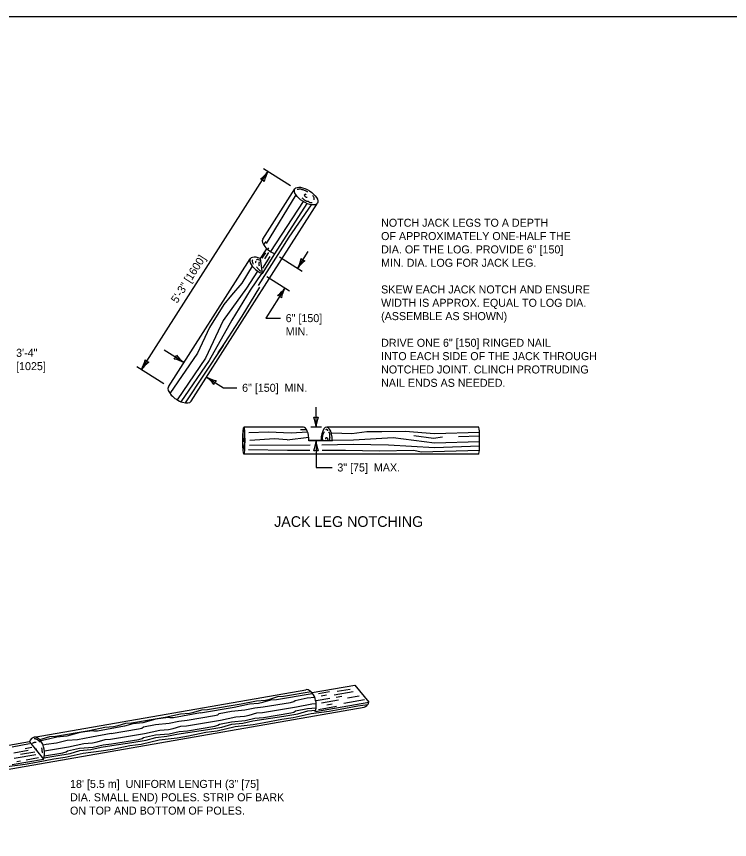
# Model space of a CAD drawing. Extents: x 49991.4 to 50021, y 49987.6 to 50011.4.
# Drawn here: x 50003.34 to 50008.69, y 49992.83 to 49999 of the extents above; entities that cross this region are included whole.
import ezdxf

# ---------------------------------------------------------------- set-up
doc = ezdxf.new("R2010")
doc.units = 0
for name, color, linetype in [('Level 1', 7, 'Continuous'), ('Level 2', 7, 'Continuous'), ('Level 3', 7, 'Continuous')]:
    doc.layers.add(name, color=color, linetype=linetype)

msp = doc.modelspace()

# ---------------------------------------------------------------- linework, layer by layer
at = {"layer": 'Level 1'}
for p, q in [((50005.1905, 49997.3295), (50005.4315, 49997.707)), ((50005.3496, 49997.2048), (50005.6009, 49997.5986)), ((50005.2014, 49997.2915), (50005.2152, 49997.313)), ((50005.1738, 49997.1841), (50005.2212, 49997.2583)), ((50005.1867, 49997.1869), (50005.2128, 49997.2278)), ((50005.2072, 49997.1826), (50005.237, 49997.2293)), ((50005.2283, 49997.2521), (50005.2365, 49997.265)), ((50004.4838, 49996.2226), (50005.097, 49997.183)), ((50004.6533, 49996.1142), (50005.3496, 49997.2048)), ((50005.141, 49997.1638), (50005.1418, 49997.164)), ((50005.1439, 49997.1757), (50005.1499, 49997.1769)), ((50005.1615, 49997.1757), (50005.1672, 49997.1734)), ((50005.1879, 49997.0719), (50005.1738, 49997.1841)), ((50005.1879, 49997.0719), (50005.282, 49997.2193)), ((50005.1907, 49997.1129), (50005.2462, 49997.1998)), ((50005.1373, 49997.1603), (50005.1374, 49997.1605)), ((50005.1375, 49997.1607), (50005.1378, 49997.1613)), ((50005.1394, 49997.1522), (50005.1375, 49997.1548)), ((50005.161, 49997.1447), (50005.161, 49997.1451)), ((50005.1676, 49997.1285), (50005.1647, 49997.1326)), ((50005.1653, 49997.157), (50005.1669, 49997.159)), ((50005.495, 49995.9203), (50005.0483, 49995.9203)), ((50005.5194, 49995.9016), (50005.4736, 49995.9016)), ((50006.8094, 49995.9203), (50005.6699, 49995.9203)), ((50005.6281, 49995.8211), (50005.537, 49995.8211)), ((50005.7119, 49995.8183), (50005.537, 49995.8183)), ((50005.6281, 49995.8211), (50005.7119, 49995.8183)), ((50006.816, 49995.8525), (50006.6578, 49995.8478)), ((50006.8094, 49995.7191), (50005.0483, 49995.7191)), ((50005.5599, 49993.9305), (50005.8806, 49993.9866)), ((50005.7483, 49993.9404), (50005.8449, 49993.9573)), ((50005.8806, 49993.9866), (50005.9865, 49993.8591)), ((50003.4771, 49993.5964), (50005.5129, 49993.9521)), ((50005.6077, 49993.9234), (50005.6902, 49993.9378)), ((50005.6283, 49993.9063), (50005.6688, 49993.9134)), ((50005.7266, 49993.9138), (50005.8681, 49993.9384)), ((50005.7419, 49993.8961), (50005.7824, 49993.9031)), ((50005.8257, 49993.891), (50005.9125, 49993.9062)), ((50005.5849, 49993.7889), (50005.9865, 49993.8591)), ((50005.5908, 49993.8718), (50005.6925, 49993.8896)), ((50005.6318, 49993.8547), (50005.7592, 49993.877)), ((50005.6714, 49993.8397), (50005.7118, 49993.8468)), ((50005.7988, 49993.8522), (50005.9524, 49993.879)), ((50000.9144, 49992.9433), (50005.951, 49993.8227)), ((50005.6076, 49993.8043), (50005.7433, 49993.8279)), ((50003.4416, 49993.5605), (50003.2869, 49993.5335)), ((50003.4436, 49993.5457), (50003.3119, 49993.5226)), ((50003.4416, 49993.5605), (50003.5478, 49993.433)), ((50003.4314, 49993.4959), (50003.3243, 49993.4772)), ((50003.4907, 49993.465), (50003.3277, 49993.4365)), ((50003.4812, 49993.4855), (50003.3745, 49993.4668)), ((50003.46, 49993.5189), (50003.411, 49993.5104)), ((50003.3119, 49993.3918), (50003.5478, 49993.433)), ((50003.3757, 49993.4167), (50003.3464, 49993.4116)), ((50003.5108, 49993.4407), (50003.4181, 49993.4244))]:
    msp.add_line(p, q, dxfattribs=at)
msp.add_lwpolyline([(49999.3835, 49998.9992), (50016.7501, 49998.9992), (50016.7501, 49987.7988), (49999.3835, 49987.7988)], close=True, dxfattribs=at)
for points in [[(50005.4393, 49997.6622), (50005.2168, 49997.2978)], [(50005.4925, 49997.6126), (50005.2499, 49997.2362)], [(50005.5219, 49997.5972), (50005.2792, 49997.2205)], [(50005.5546, 49997.5873), (50005.3858, 49997.346), (50005.1567, 49996.9819)], [(50005.1123, 49997.1264), (50005.0346, 49996.9991), (50004.9559, 49996.9091), (50004.8996, 49996.8396), (50004.7922, 49996.6675), (50004.7028, 49996.4757), (50004.4955, 49996.1723)], [(50005.1526, 49997.0894), (50005.069, 49996.9637), (50004.8934, 49996.7212), (50004.762, 49996.4385), (50004.5485, 49996.126)], [(50005.1815, 49997.0734), (50005.097, 49996.9463), (50004.9592, 49996.7218), (50004.7896, 49996.4207), (50004.5779, 49996.1114)], [(50005.167, 49996.9711), (50005.0336, 49996.7532), (50004.8554, 49996.4766), (50004.8933, 49996.5334), (50004.6098, 49996.1025)], [(50005.5272, 49995.8842), (50005.4029, 49995.8764), (50005.2327, 49995.8841), (50005.0861, 49995.8786)], [(50005.7082, 49995.877), (50005.8585, 49995.8739), (50005.97, 49995.8869), (50006.0835, 49995.8888), (50006.259, 49995.8902), (50006.4782, 49995.8719), (50006.8149, 49995.8824)], [(50005.3725, 49995.8266), (50005.2783, 49995.8322), (50005.0949, 49995.8198)], [(50005.3725, 49995.8266), (50005.5355, 49995.8461)], [(50005.7165, 49995.8231), (50005.8698, 49995.8259), (50006.1687, 49995.8434), (50006.4777, 49995.802), (50006.8164, 49995.8126)], [(50006.5385, 49995.8455), (50006.471, 49995.8346), (50006.3225, 49995.8558)], [(50005.0829, 49995.7521), (50005.3766, 49995.7493), (50005.5445, 49995.7486)], [(50005.0921, 49995.7851), (50005.5455, 49995.7869)], [(50005.6341, 49995.7886), (50005.8694, 49995.793), (50006.1328, 49995.7882), (50006.4779, 49995.7692), (50006.8159, 49995.78)], [(50005.6353, 49995.7481), (50005.8108, 49995.7473)], [(50005.8108, 49995.7473), (50006.0663, 49995.7424), (50006.3231, 49995.7472), (50006.3792, 49995.7355), (50006.8144, 49995.7486)], [(50004.7765, 49993.8042), (50005.0296, 49993.8461), (50005.1448, 49993.8701), (50005.2101, 49993.8751), (50005.2448, 49993.8824), (50005.3034, 49993.9005), (50005.346, 49993.9038)], [(50005.1942, 49993.8236), (50005.3984, 49993.8573), (50005.4231, 49993.8641), (50005.4345, 49993.8727), (50005.5246, 49993.8911), (50005.5801, 49993.8958)], [(50005.2935, 49993.8795), (50005.5467, 49993.9213), (50005.5643, 49993.925)], [(50005.346, 49993.9038), (50005.5529, 49993.938)], [(50004.724, 49993.78), (50004.9771, 49993.8219), (50005.0923, 49993.8458), (50005.1577, 49993.8507), (50005.1923, 49993.858), (50005.2511, 49993.8762), (50005.2935, 49993.8795)], [(50005.1895, 49993.7818), (50005.4425, 49993.8235), (50005.5577, 49993.8475), (50005.5912, 49993.8501)], [(50005.7717, 49993.8061), (50005.9026, 49993.8323), (50005.9783, 49993.8425)], [(50004.724, 49993.78), (50004.5206, 49993.7425), (50004.4949, 49993.7405), (50004.4814, 49993.7446), (50004.3903, 49993.7314), (50004.2911, 49993.7049), (50004.2165, 49993.6958), (50004.1547, 49993.6804)], [(50004.207, 49993.7049), (50004.4602, 49993.7467), (50004.5753, 49993.7707), (50004.6407, 49993.7756), (50004.6753, 49993.7829), (50004.7341, 49993.801), (50004.7765, 49993.8042)], [(50004.6201, 49993.6823), (50004.8732, 49993.7239), (50004.9883, 49993.748), (50005.0537, 49993.7529), (50005.0883, 49993.7604), (50005.1472, 49993.7784), (50005.1895, 49993.7818)], [(50004.6249, 49993.7242), (50004.8291, 49993.7579), (50004.8536, 49993.7647), (50004.8652, 49993.7733), (50004.9553, 49993.7918), (50005.0576, 49993.8004), (50005.1309, 49993.8171), (50005.1942, 49993.8236)], [(50005.1959, 49993.7447), (50005.4, 49993.7783), (50005.4248, 49993.7851), (50005.4362, 49993.7938), (50005.5264, 49993.8122), (50005.5913, 49993.8177)], [(50005.1981, 49993.732), (50005.3481, 49993.7549), (50005.4544, 49993.772), (50005.5281, 49993.7943), (50005.5882, 49993.7999)], [(50005.2024, 49993.7066), (50005.3332, 49993.7327), (50005.4188, 49993.7446), (50005.5531, 49993.775), (50005.6884, 49993.7916), (50005.7717, 49993.8061)], [(50004.0556, 49993.6249), (50004.2597, 49993.6584), (50004.2844, 49993.6654), (50004.2958, 49993.6739), (50004.386, 49993.6924), (50004.4882, 49993.701), (50004.5615, 49993.7177), (50004.6249, 49993.7242)], [(50004.6265, 49993.6451), (50004.8306, 49993.6787), (50004.8553, 49993.6856), (50004.8669, 49993.6942), (50004.957, 49993.7127), (50005.0592, 49993.7213), (50005.1324, 49993.7381), (50005.1959, 49993.7447)], [(50004.6287, 49993.6325), (50004.7786, 49993.6554), (50004.885, 49993.6726), (50004.9588, 49993.6949), (50005.0409, 49993.7024), (50005.117, 49993.7197), (50005.1981, 49993.732)], [(50004.1547, 49993.6804), (50003.9512, 49993.6429), (50003.9256, 49993.641), (50003.9121, 49993.645), (50003.821, 49993.6318), (50003.7218, 49993.6054), (50003.6473, 49993.5962), (50003.5855, 49993.5809)], [(50003.6376, 49993.6054), (50003.8907, 49993.6471), (50004.0059, 49993.6712), (50004.0712, 49993.6761), (50004.1059, 49993.6835), (50004.1646, 49993.7016), (50004.207, 49993.7049)], [(50004.0506, 49993.5827), (50004.3037, 49993.6246), (50004.4189, 49993.6485), (50004.4843, 49993.6535), (50004.519, 49993.6609), (50004.5777, 49993.679), (50004.6201, 49993.6823)], [(50004.6331, 49993.6072), (50004.7639, 49993.6333), (50004.8495, 49993.6451), (50004.9838, 49993.6756), (50005.1189, 49993.6921), (50005.2024, 49993.7066)], [(50003.5179, 49993.58), (50003.5365, 49993.584), (50003.5952, 49993.6021), (50003.6376, 49993.6054)], [(50004.0556, 49993.6249), (50003.9068, 49993.5955), (50003.801, 49993.5758), (50003.7241, 49993.5716), (50003.6442, 49993.5509), (50003.5667, 49993.5413), (50003.5442, 49993.5369)], [(50004.0572, 49993.5457), (50004.2612, 49993.5793), (50004.286, 49993.5863), (50004.2975, 49993.5948), (50004.3876, 49993.6132), (50004.4898, 49993.6219), (50004.5631, 49993.6386), (50004.6265, 49993.6451)], [(50004.0594, 49993.5331), (50004.2093, 49993.5559), (50004.3157, 49993.5731), (50004.3894, 49993.5954), (50004.4715, 49993.6031), (50004.5476, 49993.6203), (50004.6287, 49993.6325)], [(50004.0638, 49993.5077), (50004.1945, 49993.5338), (50004.2801, 49993.5454), (50004.4144, 49993.5762), (50004.5496, 49993.5927), (50004.6331, 49993.6072)], [(50003.5855, 49993.5809), (50003.5265, 49993.57)], [(50003.5508, 49993.4429), (50003.6399, 49993.4564), (50003.7463, 49993.4738), (50003.8199, 49993.4958), (50003.9022, 49993.5037), (50003.9784, 49993.5208), (50004.0594, 49993.5331)], [(50003.5536, 49993.457), (50003.692, 49993.4799), (50003.7167, 49993.4868), (50003.7281, 49993.4952), (50003.8183, 49993.5138), (50003.9205, 49993.5224), (50003.9938, 49993.5391), (50004.0572, 49993.5457)], [(50003.554, 49993.4953), (50003.7345, 49993.5251), (50003.8497, 49993.5491), (50003.915, 49993.554), (50003.9496, 49993.5615), (50004.0083, 49993.5795), (50004.0506, 49993.5827)], [(50003.4943, 49993.4082), (50003.6251, 49993.4343), (50003.7108, 49993.446), (50003.8452, 49993.4766), (50003.9803, 49993.4932), (50004.0638, 49993.5077)], [(50002.925, 49993.3087), (50003.0558, 49993.3348), (50003.1413, 49993.3467), (50003.2756, 49993.3771), (50003.4108, 49993.3937), (50003.4943, 49993.4082)]]:
    msp.add_lwpolyline(points, dxfattribs=at)
for centre, radius, start, end in [((50005.1422, 49997.1589), 0.005, 103.51797, 151.39124), ((50005.1538, 49997.1573), 0.02, 67.59208, 101.26791), ((50005.1415, 49997.1578), 0.005, 149.082, 215.75362), ((50005.1331, 49997.1631), 0.005, 329.082, 331.39124), ((50005.181, 49997.1446), 0.02, 141.84409, 178.59483), ((50005.181, 49997.1442), 0.02, 178.59483, 215.47596)]:
    msp.add_arc(centre, radius, start, end, dxfattribs=at)
for centre, major_axis, ratio in [((50005.5162, 49997.6528), (-0.0847, 0.0542), 0.462929), ((50005.0483, 49995.8197), (0, 0.1006), 0.069439)]:
    msp.add_ellipse(centre, major_axis=major_axis, ratio=ratio, dxfattribs=at)
for centre, major_axis, ratio, start_param, end_param in [((50005.2752, 49997.2753), (-0.0847, 0.0542), 0.462929, 0, 1.935586), ((50005.1811, 49997.1279), (-0.0847, 0.0542), 0.462929, 5.082678, 8.21875), ((50004.5685, 49996.1684), (-0.0847, 0.0542), 0.462929, 6.283184, 9.425644), ((50005.4951, 49995.8197), (-0.0001, 0.1006), 0.416637, 4.698139, 6.283283), ((50005.67, 49995.8197), (-0.0001, 0.1006), 0.416637, 4.698139, 7.839732), ((50006.8094, 49995.8197), (0, 0.1006), 0.069439, 3.141147, 6.283606), ((50005.5317, 49993.8525), (-0.0175, 0.0999), 0.577493, 3.925489, 6.306126), ((50005.9334, 49993.9226), (-0.0175, 0.0999), 0.577493, 3.141466, 3.926391), ((50003.4946, 49993.4966), (-0.0175, 0.0999), 0.577493, 3.925612, 7.06337)]:
    msp.add_ellipse(centre, major_axis=major_axis, ratio=ratio, start_param=start_param, end_param=end_param, dxfattribs=at)
for points in [[(50005.5291, 49997.6809), (50005.5037, 49997.6954), (50005.4815, 49997.7024), (50005.4722, 49997.7049), (50005.4493, 49997.7012)], [(50005.5163, 49997.662), (50005.509, 49997.6662), (50005.5032, 49997.663), (50005.5026, 49997.6559), (50005.5061, 49997.652), (50005.515, 49997.6442), (50005.5225, 49997.6436)], [(50005.5633, 49997.6585), (50005.5684, 49997.6509), (50005.5734, 49997.6416), (50005.5745, 49997.6307), (50005.5741, 49997.6253)], [(50005.4825, 49997.6394), (50005.4933, 49997.6332), (50005.5039, 49997.6234), (50005.5167, 49997.6171), (50005.5185, 49997.6151), (50005.5241, 49997.6147), (50005.537, 49997.6101), (50005.5424, 49997.6061), (50005.5517, 49997.6037), (50005.5612, 49997.6047)], [(50005.1214, 49997.1414), (50005.1175, 49997.1496), (50005.1139, 49997.1596), (50005.1145, 49997.1705), (50005.1157, 49997.1758)], [(50005.1445, 49997.1218), (50005.1523, 49997.1123), (50005.1616, 49997.1018), (50005.1737, 49997.093), (50005.1773, 49997.091)], [(50005.0437, 49995.824), (50005.0439, 49995.8532), (50005.0448, 49995.8757), (50005.0453, 49995.8848), (50005.0476, 49995.9022)], [(50005.6399, 49995.826), (50005.6393, 49995.8487), (50005.6457, 49995.874), (50005.6527, 49995.8863)], [(50005.6637, 49995.9029), (50005.6639, 49995.9032), (50005.6645, 49995.9037), (50005.6653, 49995.9042), (50005.6657, 49995.9045), (50005.6661, 49995.9047), (50005.667, 49995.9051), (50005.6678, 49995.9054), (50005.6682, 49995.9054), (50005.6684, 49995.9055), (50005.6685, 49995.9055), (50005.6686, 49995.9055), (50005.6689, 49995.9054), (50005.6693, 49995.9054), (50005.67, 49995.9051), (50005.6705, 49995.9049), (50005.6709, 49995.9047), (50005.6713, 49995.9044), (50005.6716, 49995.9042), (50005.6731, 49995.9031), (50005.6737, 49995.9026), (50005.674, 49995.9023), (50005.6742, 49995.9021), (50005.6748, 49995.9014), (50005.675, 49995.9011), (50005.6752, 49995.9008), (50005.6754, 49995.9002), (50005.6755, 49995.8996), (50005.6755, 49995.8989), (50005.6754, 49995.8983), (50005.6754, 49995.8977), (50005.6755, 49995.8971), (50005.6763, 49995.8941)], [(50005.0471, 49995.8246), (50005.0472, 49995.833), (50005.0481, 49995.8362), (50005.049, 49995.8328), (50005.0492, 49995.8278), (50005.0495, 49995.8161), (50005.0489, 49995.8095)], [(50005.0527, 49995.841), (50005.0526, 49995.8285), (50005.053, 49995.8143), (50005.0528, 49995.8001), (50005.0529, 49995.7976), (50005.0525, 49995.7926), (50005.052, 49995.7793), (50005.0521, 49995.7726), (50005.0516, 49995.7634), (50005.0507, 49995.756)], [(50005.0438, 49995.7831), (50005.0443, 49995.7747), (50005.0451, 49995.7655), (50005.0464, 49995.7587), (50005.0471, 49995.7562)], [(50003.4777, 49993.5867), (50003.4836, 49993.5856), (50003.4912, 49993.5841), (50003.4955, 49993.5826), (50003.5003, 49993.58), (50003.5036, 49993.5769), (50003.5068, 49993.5733), (50003.5117, 49993.5692), (50003.5133, 49993.5677), (50003.5155, 49993.5646), (50003.5176, 49993.5605), (50003.5182, 49993.5589)], [(50003.4639, 49993.5513), (50003.4654, 49993.5524), (50003.4727, 49993.5567), (50003.4801, 49993.5581), (50003.4865, 49993.5592), (50003.4924, 49993.557)], [(50003.4834, 49993.5103), (50003.4835, 49993.5103), (50003.4836, 49993.5104), (50003.4838, 49993.5105), (50003.4841, 49993.5107), (50003.4846, 49993.5109), (50003.4849, 49993.5109), (50003.4852, 49993.5109), (50003.4857, 49993.5109), (50003.486, 49993.5109), (50003.4863, 49993.5109), (50003.4866, 49993.5108), (50003.4869, 49993.5108), (50003.4874, 49993.5107), (50003.488, 49993.5105), (50003.4883, 49993.5104), (50003.4887, 49993.5104), (50003.4894, 49993.5101), (50003.4901, 49993.5098), (50003.4904, 49993.5095), (50003.4906, 49993.5094), (50003.4908, 49993.5093), (50003.4912, 49993.5089), (50003.4916, 49993.5084), (50003.4919, 49993.508), (50003.492, 49993.5078), (50003.4922, 49993.5076), (50003.4924, 49993.5071), (50003.4926, 49993.5067), (50003.4927, 49993.5062), (50003.4928, 49993.5057), (50003.4929, 49993.5045), (50003.4929, 49993.5033), (50003.4929, 49993.5021), (50003.4928, 49993.5009), (50003.4928, 49993.5002), (50003.4927, 49993.4995), (50003.4927, 49993.4991)], [(50003.5385, 49993.4791), (50003.539, 49993.4836), (50003.5379, 49993.4884), (50003.5364, 49993.4999), (50003.5362, 49993.503), (50003.5355, 49993.5119), (50003.5318, 49993.5179)]]:
    msp.add_spline(points, degree=3, dxfattribs=at)
for points in [[(50005.6829, 49995.8851), (50005.6902, 49995.8791), (50005.6907, 49995.8762), (50005.6906, 49995.8723), (50005.6905, 49995.8699), (50005.6905, 49995.8675), (50005.6904, 49995.8652), (50005.6903, 49995.864), (50005.6902, 49995.8628), (50005.6902, 49995.8616), (50005.6901, 49995.8604), (50005.6901, 49995.8592), (50005.6901, 49995.858), (50005.6901, 49995.8533), (50005.6906, 49995.8486), (50005.6914, 49995.8439), (50005.6914, 49995.8436), (50005.6915, 49995.8434), (50005.6916, 49995.8432), (50005.6917, 49995.843), (50005.6919, 49995.8428), (50005.692, 49995.8426), (50005.6921, 49995.8424), (50005.6922, 49995.8422), (50005.6923, 49995.842), (50005.6924, 49995.8418), (50005.6925, 49995.8415), (50005.6925, 49995.8413), (50005.6925, 49995.8409), (50005.6924, 49995.8405), (50005.6923, 49995.8401), (50005.6921, 49995.8397), (50005.692, 49995.8393), (50005.6918, 49995.8388), (50005.6916, 49995.8384), (50005.6915, 49995.838), (50005.6913, 49995.8376), (50005.6911, 49995.8372), (50005.691, 49995.8368), (50005.691, 49995.8364), (50005.6907, 49995.8341), (50005.6906, 49995.8319), (50005.6905, 49995.8297), (50005.6905, 49995.8286), (50005.6905, 49995.8275), (50005.6905, 49995.8264), (50005.6905, 49995.8252), (50005.6905, 49995.8241), (50005.6907, 49995.823), (50005.6909, 49995.8217), (50005.6913, 49995.8203), (50005.6917, 49995.819)], [(50005.6629, 49995.8313), (50005.663, 49995.8327), (50005.663, 49995.8341), (50005.6631, 49995.8355), (50005.6631, 49995.8362), (50005.6631, 49995.8368), (50005.6632, 49995.8375), (50005.6632, 49995.8379), (50005.6632, 49995.8382), (50005.6632, 49995.8386), (50005.6632, 49995.8388), (50005.6633, 49995.8389), (50005.6633, 49995.8391), (50005.6633, 49995.8393), (50005.6633, 49995.8395), (50005.6633, 49995.8396), (50005.6633, 49995.84), (50005.6636, 49995.8403), (50005.6639, 49995.8406), (50005.6643, 49995.841), (50005.6647, 49995.8413), (50005.6653, 49995.8417), (50005.6658, 49995.842), (50005.6663, 49995.8423), (50005.667, 49995.8425), (50005.6672, 49995.8426), (50005.6675, 49995.8427), (50005.6678, 49995.8428), (50005.6679, 49995.8428), (50005.6681, 49995.8428), (50005.6682, 49995.8429), (50005.6683, 49995.8429), (50005.6683, 49995.8429), (50005.6684, 49995.8429), (50005.6684, 49995.8429), (50005.6684, 49995.8429), (50005.6685, 49995.8429), (50005.6685, 49995.8429), (50005.6685, 49995.8429), (50005.6686, 49995.8429), (50005.6687, 49995.8429), (50005.6688, 49995.8429), (50005.6689, 49995.8429), (50005.6691, 49995.8429), (50005.6692, 49995.8428), (50005.6693, 49995.8428), (50005.6696, 49995.8427), (50005.6699, 49995.8426), (50005.67, 49995.8425), (50005.6706, 49995.8422), (50005.6712, 49995.842), (50005.6716, 49995.8417), (50005.6721, 49995.8413), (50005.6726, 49995.8409), (50005.6731, 49995.8405), (50005.6733, 49995.8403), (50005.6735, 49995.8402), (50005.6737, 49995.84), (50005.6738, 49995.8399), (50005.6739, 49995.8398), (50005.674, 49995.8397), (50005.6741, 49995.8397), (50005.6742, 49995.8396), (50005.6742, 49995.8395), (50005.6747, 49995.8391), (50005.675, 49995.8387), (50005.6752, 49995.8382), (50005.6754, 49995.8378), (50005.6755, 49995.8374), (50005.6755, 49995.837), (50005.6755, 49995.8366), (50005.6754, 49995.8362), (50005.6754, 49995.8357), (50005.6754, 49995.8355), (50005.6754, 49995.8353), (50005.6754, 49995.8351), (50005.6754, 49995.8349), (50005.6755, 49995.8347), (50005.6755, 49995.8345), (50005.6756, 49995.8338), (50005.6758, 49995.8331), (50005.676, 49995.8324), (50005.6763, 49995.8317), (50005.6765, 49995.831), (50005.6767, 49995.8303), (50005.677, 49995.8296), (50005.6772, 49995.8289), (50005.6774, 49995.8282), (50005.6776, 49995.8275), (50005.6777, 49995.8268), (50005.6778, 49995.8261)]]:
    msp.add_open_spline(points, degree=3, dxfattribs=at)
at = {"layer": 'Level 3'}
for p, q in [((50005.3977, 49997.7285), (50005.1954, 49997.8576)), ((50004.2815, 49996.3517), (50005.2291, 49997.8361)), ((50005.4515, 49997.1111), (50005.5322, 49997.2375)), ((50005.3157, 49997.1978), (50005.4852, 49997.0896)), ((50005.2216, 49997.0504), (50005.3911, 49996.9422)), ((50004.6, 49996.4046), (50004.4526, 49996.4987)), ((50004.4501, 49996.2441), (50004.2478, 49996.3732)), ((50005.5899, 49995.9203), (50005.5899, 49996.0703)), ((50005.6299, 49995.9203), (50005.5499, 49995.9203))]:
    msp.add_line(p, q, dxfattribs=at)
for points in [[(50005.3574, 49996.9637), (50005.2132, 49996.7379), (50005.3228, 49996.7379)], [(50004.7696, 49996.2964), (50004.896, 49996.2157), (50004.996, 49996.2157)], [(50005.5899, 49995.8183), (50005.5899, 49995.6183), (50005.7099, 49995.6183)]]:
    msp.add_lwpolyline(points, dxfattribs=at)
for centre, radius, start, end in [((50005.0468, 49997.9633), 0.2223, 304.90098, 325.08449), ((50005.1601, 49997.728), 0.0548, 39.58379, 75.30615), ((50005.4315, 49997.7206), 0.233, 150.27228, 169.52213), ((50005.2593, 49997.2229), 0.2223, 329.80545, 349.98896), ((50005.6414, 49996.9762), 0.233, 125.36781, 144.61766), ((50005.5205, 49997.2192), 0.0548, 219.58379, 255.30615), ((50005.1674, 49997.0986), 0.233, 305.36781, 324.61766), ((50005.5495, 49996.8519), 0.2223, 149.80545, 169.98896), ((50005.2884, 49996.8556), 0.0548, 39.58379, 75.30615), ((50004.0791, 49996.4672), 0.233, 330.27228, 349.52213), ((50004.3505, 49996.4598), 0.0548, 219.58379, 255.30615), ((50004.4919, 49996.4736), 0.0548, 309.58379, 345.30615), ((50004.4882, 49996.2125), 0.2223, 59.80545, 79.98896), ((50004.7349, 49996.5946), 0.233, 215.36781, 234.61766), ((50004.4638, 49996.2245), 0.2223, 124.90098, 145.08449), ((50004.6423, 49996.1141), 0.2223, 34.90098, 55.08449), ((50004.8851, 49996.4987), 0.233, 240.27228, 259.52213), ((50004.8777, 49996.2274), 0.0548, 129.58379, 165.30615), ((50005.5899, 49996.0485), 0.0548, 252.13882, 287.86118), ((50005.3572, 49995.9088), 0.233, 2.82731, 22.07716), ((50005.812, 49995.9111), 0.2223, 157.45601, 177.63952), ((50005.3678, 49995.8275), 0.2223, 337.45601, 357.63952), ((50005.8226, 49995.8298), 0.233, 182.82731, 202.07716), ((50005.5899, 49995.6901), 0.0548, 72.13882, 107.86118)]:
    msp.add_arc(centre, radius, start, end, dxfattribs=at)

# ---------------------------------------------------------------- texts
at = {"layer": 'Level 2'}
for s, height, p in [('NOTCH JACK LEGS TO A DEPTH', 0.06, (50006.0778, 49997.4229)), ('OF APPROXIMATELY ONE-HALF THE', 0.06, (50006.0778, 49997.3229)), ('DIA. OF THE LOG. PROVIDE 6" [150]', 0.06, (50006.0778, 49997.2229)), ('MIN. DIA. LOG FOR JACK LEG.', 0.06, (50006.0778, 49997.1229)), ('SKEW EACH JACK NOTCH AND ENSURE', 0.06, (50006.0778, 49996.9229)), ('WIDTH IS APPROX. EQUAL TO LOG DIA.', 0.06, (50006.0778, 49996.8229)), ('(ASSEMBLE AS SHOWN)', 0.06, (50006.0778, 49996.7229)), ('DRIVE ONE 6" [150] RINGED NAIL', 0.06, (50006.0778, 49996.5229)), ('3\'-4"', 0.06, (50003.3418, 49996.4478)), ('INTO EACH SIDE OF THE JACK THROUGH', 0.06, (50006.0778, 49996.4229)), ('[1025]', 0.06, (50003.3418, 49996.3478)), ('NOTCHED JOINT. CLINCH PROTRUDING', 0.06, (50006.0778, 49996.3229)), ('NAIL ENDS AS NEEDED.', 0.06, (50006.0778, 49996.2229)), ('JACK LEG NOTCHING', 0.08, (50005.2759, 49995.1729)), ('18\' [5.5 m]  UNIFORM LENGTH (3" [75]', 0.06, (50003.7463, 49993.2162)), ('DIA. SMALL END) POLES. STRIP OF BARK', 0.06, (50003.7463, 49993.1162)), ('ON TOP AND BOTTOM OF POLES.', 0.06, (50003.7463, 49993.0162))]:
    msp.add_text(s, height=height, dxfattribs=at).set_placement(p)
for s, rotation, p in [('5\'-3" [1600]', 57.44497, (50004.5487, 49996.8446)), ('6" [150]', 360, (50005.3628, 49996.7079)), ('MIN.', 360, (50005.3628, 49996.6079)), ('6" [150]  MIN.', 360, (50005.036, 49996.1857)), ('3" [75]  MAX.', 359.99934, (50005.7499, 49995.5883))]:
    msp.add_text(s, height=0.06, rotation=rotation, dxfattribs=at).set_placement(p)

doc.saveas('drawing.dxf')
